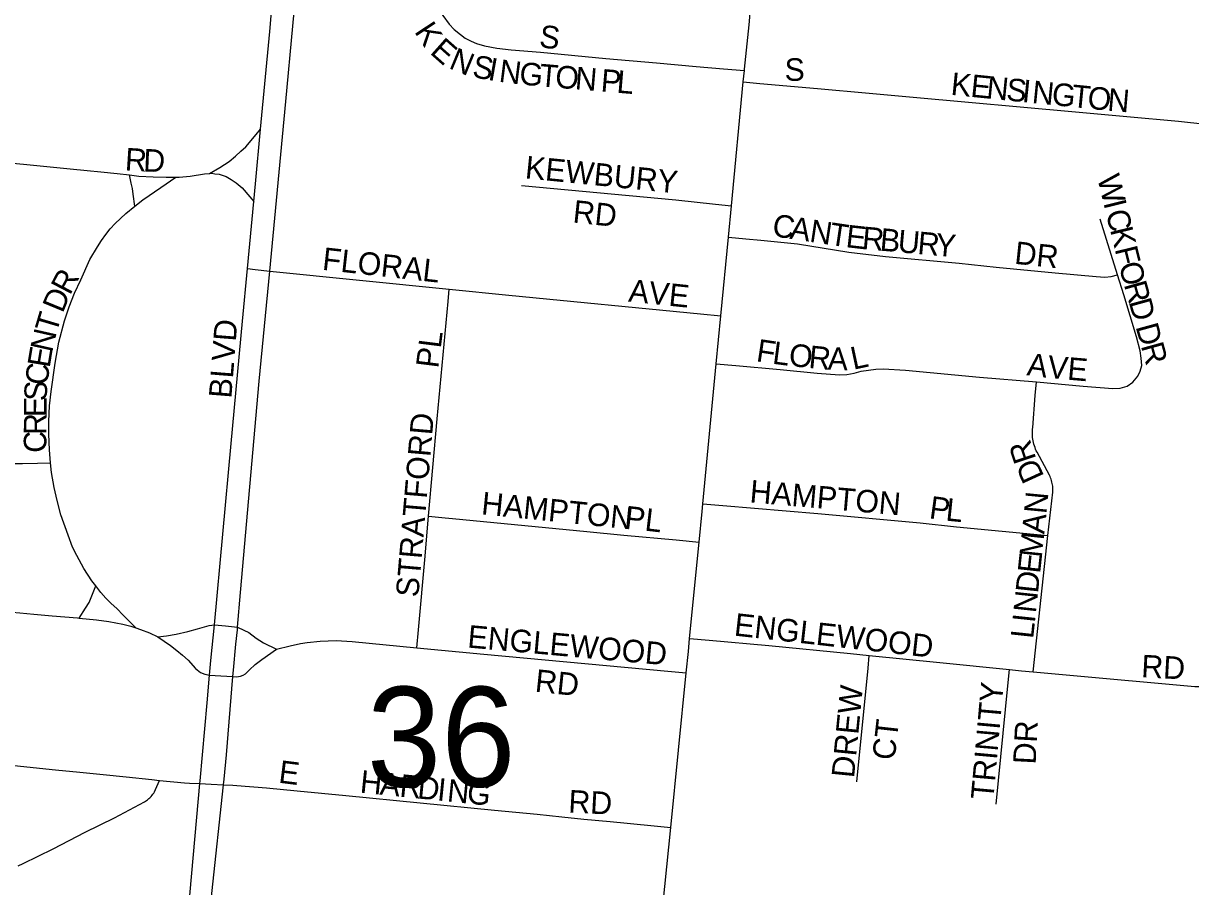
# Model space of a CAD drawing. Extents: x 1410790 to 1770854, y 566777 to 831614.
# Drawn here: x 1601254 to 1603836, y 711039 to 712950 of the extents above; entities that cross this region are included whole.
import ezdxf

# ---------------------------------------------------------------- set-up
doc = ezdxf.new("R2010")
doc.units = 0
for name, color, linetype in [('GM_X_City_Street', 7, 'Continuous'), ('GM_X_City_Street_Text', 7, 'Continuous'), ('GM_X_Section_Text', 7, 'Continuous'), ('GM_X_State_Route', 7, 'Continuous')]:
    doc.layers.add(name, color=color, linetype=linetype)

msp = doc.modelspace()

# ---------------------------------------------------------------- linework, layer by layer
at = {"layer": 'GM_X_City_Street'}
for points in [[(1601778.7, 712715.5), (1601799, 712931.8), (1601814.5, 713115.5)], [(1601798.8, 712401.6), (1601834.6, 712776.7), (1601865.2, 713110.9)], [(1602161.3, 712994.4), (1602167.7, 712986.1), (1602195.8, 712948), (1602206.9, 712936.2), (1602220.8, 712924.8), (1602231.5, 712917), (1602244.1, 712910.3), (1602256.2, 712905.4), (1602274.1, 712899.8), (1602300.9, 712894.7), (1602333, 712891.4), (1602398, 712885.7), (1602542.3, 712872.1), (1602654.3, 712862.3), (1602741.8, 712854.6), (1602802.9, 712849.3), (1602848.8, 712845.3)], [(1602846.4, 712820.2), (1602882.9, 712816.9), (1603010.5, 712805.5), (1603125.1, 712795.1), (1603222, 712786.7), (1603581.4, 712753.9), (1603694.9, 712743.5), (1603809, 712733.1), (1603922.9, 712720.7), (1604085.5, 712702.9), (1604376.2, 712670.1), (1604592.9, 712646.1), (1604785, 712626.3), (1605102.2, 712593.1)], [(1601665.7, 712617.6), (1601688.7, 712631), (1601708.8, 712644.3), (1601723, 712655.5), (1601735.2, 712666.9), (1601746, 712676.6), (1601769.1, 712704.1), (1601778.7, 712715.5)], [(1601763.7, 712555.6), (1601767.4, 712594.5), (1601778.7, 712715.5)], [(1601021.6, 712660), (1601080.3, 712654.8), (1601141.7, 712649.3), (1601209.6, 712642.7), (1601291.2, 712634.6), (1601357.1, 712628), (1601395.4, 712624.2), (1601425, 712621.2), (1601461.5, 712617.6), (1601488.4, 712614.3)], [(1601500.6, 712545.3), (1601497.1, 712572), (1601495.4, 712584.5), (1601492.7, 712595.9), (1601488.4, 712614.3)], [(1601488.4, 712614.3), (1601509.1, 712611.8), (1601541.4, 712610.1), (1601569.6, 712609), (1601591.5, 712609)], [(1601500.6, 712545.3), (1601518, 712559.2), (1601558, 712586.3), (1601591.5, 712609)], [(1601591.5, 712609), (1601598.5, 712609), (1601622.6, 712611.3), (1601654.8, 712617), (1601665.7, 712617.6)], [(1601665.7, 712617.6), (1601671, 712617.9), (1601677.8, 712617), (1601687, 712615.8), (1601702.4, 712610.5), (1601713.7, 712604.1), (1601724.5, 712596.7), (1601737.7, 712585.9), (1601754.9, 712565.8), (1601763.7, 712555.6)], [(1602355.5, 712591), (1602697, 712558.8), (1602785.1, 712549.3), (1602820.2, 712545.5)], [(1601314.3, 711977.2), (1601311.4, 712005.5), (1601310.6, 712040.2), (1601310.6, 712068.2), (1601312.1, 712102.9), (1601315.1, 712134.6), (1601324.2, 712197.3), (1601332.3, 712244), (1601345, 712291.4), (1601355.1, 712322.4), (1601367.1, 712352.8), (1601380.9, 712382.4), (1601401.2, 712426.8), (1601418, 712455.1), (1601426.6, 712468.9), (1601436, 712482.1), (1601446.2, 712494.8), (1601457.1, 712506.8), (1601480.4, 712529.1), (1601500.6, 712545.3)], [(1601749.6, 712407), (1601763.7, 712555.6)], [(1603674.2, 712392.8), (1603635.6, 712516.6)], [(1602813.5, 712476.2), (1602852.3, 712473), (1602885, 712470.2), (1602966.4, 712461.4), (1603079.7, 712443.4), (1603161.1, 712433.9), (1603324.1, 712418.7), (1603405.6, 712410.3), (1603536.1, 712397.8), (1603626.6, 712389.6), (1603645.9, 712388.1), (1603659.7, 712389.1), (1603674.2, 712392.8)], [(1601676.8, 711618.6), (1601713.3, 712019.6), (1601738.3, 712290.8), (1601749.6, 712407)], [(1601727.4, 711613.1), (1601734.4, 711689.8), (1601775.6, 712157.6), (1601798.8, 712401.6)], [(1601749.6, 712407), (1601766.7, 712405.2), (1601798.8, 712401.6)], [(1601798.8, 712401.6), (1602196.1, 712361.2)], [(1603718.7, 712168.9), (1603724.3, 712180), (1603727.9, 712192.5), (1603726.7, 712208.6), (1603724.1, 712224.6), (1603716.4, 712256), (1603687.8, 712349.1), (1603674.2, 712392.8)], [(1602150, 711859.1), (1602169.3, 712074.1), (1602193.6, 712334.3), (1602196.1, 712361.2)], [(1602196.1, 712361.2), (1602327.7, 712348.2), (1602751.7, 712306.6), (1602796.9, 712302.2)], [(1602786.7, 712196.2), (1602829.6, 712192.4), (1602927.9, 712183.9), (1603009.9, 712175.6), (1603059, 712172), (1603075.4, 712172.3), (1603091.4, 712175.3), (1603107.3, 712179.8), (1603139.6, 712184.5), (1603155.9, 712185.2), (1603205.1, 712182.4), (1603368.9, 712166.9), (1603494.7, 712156)], [(1603520.3, 711816.3), (1603531, 711912.2), (1603531.2, 711915.4), (1603531.2, 711918.6), (1603531.1, 711921.9), (1603530.8, 711925.1), (1603530.4, 711928.3), (1603529.8, 711931.5), (1603529.1, 711934.6), (1603528.2, 711937.7), (1603527.2, 711940.7), (1603526.1, 711943.8), (1603524.8, 711946.7), (1603523.3, 711949.6), (1603496.1, 712000.4), (1603494.4, 712003.8), (1603492.9, 712007.3), (1603491.6, 712010.8), (1603490.4, 712014.4), (1603489.3, 712018.1), (1603488.3, 712021.7), (1603487.5, 712025.4), (1603486.9, 712029.2), (1603486.4, 712032.9), (1603486.1, 712036.7), (1603485.9, 712040.5), (1603485.8, 712044.3), (1603485.9, 712048.1), (1603486.2, 712051.9), (1603486.6, 712055.6), (1603492.2, 712126), (1603494.7, 712156)], [(1603494.7, 712156), (1603598.3, 712147), (1603663.7, 712141.6), (1603679.9, 712142.2), (1603695.6, 712146.6), (1603707.7, 712155.7), (1603718.7, 712168.9)], [(1600937, 712026.2), (1600949.2, 712020.4), (1600965.1, 712012.4), (1600983.5, 712005.2), (1601002.6, 712000.4), (1601025.8, 711996.4), (1601052.9, 711993.3), (1601107.2, 711986.9), (1601156.7, 711982.1), (1601190.2, 711978.9), (1601230.9, 711975.7), (1601251.7, 711975.7), (1601285.2, 711976.5), (1601314.3, 711977.2)], [(1601414.1, 711704.5), (1601405.5, 711715.8), (1601387.7, 711743.3), (1601372.2, 711772.1), (1601362.7, 711790.3), (1601352.8, 711817), (1601336.8, 711861.9), (1601328.7, 711893.8), (1601321.9, 711922.5), (1601316.4, 711956), (1601314.3, 711977.2)], [(1602757.1, 711886.6), (1602801.3, 711882.9), (1603011.3, 711865), (1603237.4, 711844.4), (1603318, 711835.7), (1603520.3, 711816.3)], [(1602124.6, 711567.6), (1602128.2, 711607.4), (1602142.8, 711770.1), (1602149.3, 711850.9), (1602150, 711859.1)], [(1602150, 711859.1), (1602186.9, 711855.2), (1602203.3, 711853.5), (1602500.1, 711824.9), (1602582.4, 711817.2), (1602697.8, 711806.4), (1602748.8, 711801.5)], [(1603487.6, 711514.7), (1603520.3, 711816.3)], [(1601377.6, 711633.6), (1601391.3, 711655.4), (1601399.2, 711668.1), (1601405.7, 711682.7), (1601414.1, 711704.5)], [(1601502.5, 711612.1), (1601474.3, 711640.8), (1601461.1, 711653.7), (1601447.7, 711666.1), (1601436.1, 711677.6), (1601425.3, 711689.8), (1601414.1, 711704.5)], [(1600886.5, 711677.2), (1600904.3, 711675.5), (1600923.1, 711674), (1600967.5, 711669.5), (1601027.4, 711663.5), (1601076.8, 711659.5), (1601123.7, 711655.7), (1601166.2, 711652.5), (1601212.3, 711647.9), (1601246, 711644.7), (1601277.4, 711641.8), (1601317.3, 711638.3), (1601373.7, 711633.9), (1601377.6, 711633.6)], [(1601377.6, 711633.6), (1601415.4, 711629.6), (1601442.8, 711625.9), (1601473.8, 711619.7), (1601491.9, 711615.3), (1601502.5, 711612.1)], [(1601502.5, 711612.1), (1601512.9, 711608.4), (1601532.9, 711600.6), (1601551.4, 711592.1)], [(1601551.4, 711592.1), (1601570.8, 711594.5), (1601591.6, 711597.7), (1601617.6, 711603.6), (1601638.9, 711609.3), (1601654.4, 711613.9), (1601665.2, 711617.1), (1601676.8, 711618.6)], [(1601665.6, 711507.1), (1601668.8, 711539.4), (1601676.8, 711618.6)], [(1601676.8, 711618.6), (1601701.4, 711616.4)], [(1601701.4, 711616.4), (1601727.4, 711613.1)], [(1601717.4, 711504), (1601718.7, 711518.1), (1601724.1, 711575.4), (1601727.4, 711607.7), (1601727.4, 711613.1)], [(1601727.4, 711613.1), (1601741.5, 711607), (1601752.5, 711601.2), (1601768.7, 711589.3), (1601785.4, 711578.4), (1601813.7, 711564.4)], [(1601551.4, 711592.1), (1601579.7, 711573), (1601593.5, 711561.6), (1601606.3, 711551.4), (1601618.4, 711540.3), (1601635, 711522), (1601645.4, 711513.3), (1601655.1, 711509), (1601665.6, 711507.1)], [(1602727.7, 711588), (1602770.9, 711584.2), (1602902.6, 711572.4), (1603083.6, 711554.7), (1603124.9, 711550.6)], [(1601717.4, 711504), (1601725.2, 711503.6), (1601734.3, 711505), (1601740.1, 711507.2), (1601745.1, 711510.1), (1601754.1, 711518.8), (1601766.8, 711530.6), (1601781.5, 711541.9), (1601813.7, 711564.4)], [(1601813.7, 711564.4), (1601844.4, 711572.2), (1601867, 711577.4), (1601881.7, 711579.6), (1601910.7, 711582.2), (1601945.9, 711583.5), (1601980.9, 711581.6), (1602124.6, 711567.6)], [(1602124.6, 711567.6), (1602272.2, 711553.2), (1602679.6, 711515.6), (1602720.1, 711511.9)], [(1603097.8, 711271.1), (1603122.2, 711522.4), (1603124.9, 711550.6)], [(1603124.9, 711550.6), (1603281, 711534.9), (1603434.8, 711519.7)], [(1603405.8, 711221.9), (1603431.3, 711483.8), (1603434.8, 711519.7)], [(1603434.8, 711519.7), (1603462, 711517), (1603487.6, 711514.7)], [(1603487.6, 711514.7), (1603560.7, 711508), (1603845.3, 711482.3), (1603860.8, 711482), (1603879.8, 711484), (1603894.2, 711487.3), (1603935.8, 711506.2), (1603972.6, 711522.6)], [(1601644.4, 711267), (1601645, 711272.9), (1601660.5, 711445.6), (1601665.6, 711507.1)], [(1601665.6, 711507.1), (1601690.5, 711505.4)], [(1601690.5, 711505.4), (1601717.4, 711504)], [(1601696.6, 711264.7), (1601697.9, 711277.1), (1601703.6, 711330.4), (1601717.4, 711504)], [(1600541.3, 711374.7), (1600592, 711369.6), (1600706.1, 711358.9), (1600742.6, 711355.5), (1600784.5, 711351.5), (1600867.4, 711343.8), (1600980.4, 711331.6), (1601045.5, 711325.2), (1601191.2, 711311.7), (1601325.1, 711297.9), (1601378.9, 711292.3), (1601430.3, 711287), (1601481.6, 711281.7), (1601537.8, 711276), (1601555.1, 711274.2)], [(1601242.8, 711084.8), (1601253.8, 711089.9), (1601319.8, 711122.6), (1601390.6, 711159.5), (1601455.2, 711191.3), (1601521.6, 711226.8), (1601526, 711229.6), (1601528.3, 711231.3), (1601529.9, 711232.6), (1601531.6, 711233.9), (1601533.5, 711235.6), (1601536.4, 711238.5), (1601539, 711241.5), (1601540.5, 711243.4), (1601541.5, 711244.9), (1601542.2, 711245.9), (1601543, 711247.1), (1601543.9, 711248.8), (1601546.3, 711254.3), (1601555.1, 711274.2)], [(1601555.1, 711274.2), (1601610.4, 711268.5), (1601621.6, 711267.7), (1601644.4, 711267)], [(1601615.4, 710945), (1601644.4, 711267)], [(1601644.4, 711267), (1601669.6, 711266.1), (1601696.6, 711264.7)], [(1601663.7, 710940.6), (1601671, 711023.6), (1601696.6, 711264.7)], [(1601696.6, 711264.7), (1601717.4, 711263.6), (1601725.9, 711263.2), (1601791.4, 711257.4), (1601859.9, 711250.9), (1601967.3, 711240.8), (1602295.8, 711208.4), (1602390.4, 711199.1), (1602445, 711193.7), (1602494, 711188.7), (1602551.8, 711183), (1602589.2, 711179.4), (1602656.8, 711172.7), (1602685.8, 711169.8)]]:
    msp.add_lwpolyline(points, dxfattribs=at)
at = {"layer": 'GM_X_State_Route'}
msp.add_lwpolyline([(1602654.5, 710858.1), (1602685.8, 711169.8), (1602720.1, 711511.9), (1602724.8, 711559.6), (1602727.7, 711588), (1602748.8, 711801.5), (1602755.5, 711869.5), (1602757.1, 711886.6), (1602786.7, 712196.2), (1602796.9, 712302.2), (1602813.5, 712476.2), (1602820.2, 712545.5), (1602846.4, 712820.2), (1602848.8, 712845.3), (1602849.2, 712848.7), (1602859.4, 712946.5), (1602868.8, 713060.8)], dxfattribs=at)

# ---------------------------------------------------------------- texts
at = {"layer": 'GM_X_City_Street_Text'}
for s, rotation, p in [('K', 303.5627, (1602117.6, 712931.5)), ('S', 352.8783, (1602393.3, 712897.3)), ('E', 318.4859, (1602151.3, 712884.1)), ('N', 337.4623, (1602192.9, 712851.2)), ('S', 350.1365, (1602245.1, 712831)), ('I', 349.8046, (1602279.7, 712825)), ('N', 352.8025, (1602304.2, 712820.6)), ('G', 354.4515, (1602349.4, 712814.9)), ('T', 355.1258, (1602393.8, 712810.6)), ('O', 355.2289, (1602429, 712807.6)), ('N', 355.2407, (1602472.8, 712804)), ('S', 0, (1602937.7, 712822.5)), ('P', 355.2137, (1602529.9, 712799.2)), ('L', 355.2533, (1602565, 712796.3)), ('K', 354.2416, (1603303.9, 712791.7)), ('E', 354.2615, (1603347.6, 712787.3)), ('N', 354.2416, (1603382.7, 712783.7)), ('S', 354.2615, (1603426.5, 712779.3)), ('I', 354.2198, (1603461.5, 712775.8)), ('N', 354.2598, (1603483.4, 712773.6)), ('G', 354.2416, (1603527.2, 712769.2)), ('T', 354.2615, (1603571, 712764.8)), ('O', 354.2416, (1603606, 712761.2)), ('N', 355.0372, (1603650.5, 712756.7)), ('R', 356.4524, (1601477.6, 712624.5)), ('D', 357.7383, (1601518.4, 712622)), ('KEWBURY', 354.2894, (1602362.3, 712606.9)), ('W', 283.7671, (1603628.9, 712608.6)), ('RD', 353.9946, (1602467.8, 712509.1)), ('I', 283.7987, (1603642.5, 712553)), ('C', 351.2963, (1602908.4, 712479.2)), ('A', 351.2957, (1602947.5, 712473.3)), ('N', 351.2957, (1602991, 712466.6)), ('C', 283.7829, (1603647.7, 712531.6)), ('T', 351.5662, (1603034.7, 712459.9)), ('E', 353.6134, (1603071.5, 712454.5)), ('R', 354.864, (1603107.7, 712450.4)), ('B', 354.9007, (1603147.1, 712446.9)), ('U', 354.9023, (1603186.6, 712443.3)), ('K', 283.7712, (1603657.2, 712493.2)), ('R', 354.9007, (1603230.4, 712439.4)), ('Y', 354.9023, (1603269.8, 712435.9)), ('DR', 353.9946, (1603444.7, 712417.7)), ('FLORAL', 353.6594, (1601913.6, 712404.5)), ('F', 283.7686, (1603667.6, 712450.4)), ('O', 284.8811, (1603676.3, 712415.2)), ('R', 62.4575, (1601357, 712346.4)), ('D', 67.6222, (1601340.8, 712306.8)), ('AVE', 354.0969, (1602591.1, 712334.1)), ('R', 285.7844, (1603687.8, 712371.9)), ('D', 285.42, (1603698.5, 712333.8)), ('T', 73.4918, (1601327, 712261.8)), ('BLVD', 85.4883, (1601713.9, 712118.7)), ('D', 285.3989, (1603713.7, 712278.7)), ('N', 77.1938, (1601317.5, 712219.8)), ('PL', 82.8783, (1602171.6, 712185.1)), ('E', 80.614, (1601311.9, 712185.8)), ('F', 351.3328, (1602873.2, 712202)), ('L', 352.553, (1602909.1, 712196.6)), ('O', 354.158, (1602945.6, 712191.8)), ('R', 354.35, (1602989.5, 712187.3)), ('A', 358.1238, (1603032.5, 712183.2)), ('L', 12.0374, (1603089.7, 712182.9)), ('R', 285.4159, (1603725.4, 712236.3)), ('A', 352.6798, (1603472.1, 712171.1)), ('V', 354.778, (1603517.8, 712165.3)), ('E', 355.0229, (1603561.8, 712161.3)), ('C', 82.6461, (1601306.9, 712147)), ('S', 87.2945, (1601305.3, 712112.9)), ('E', 89.6721, (1601305.1, 712078.2)), ('R', 89.6843, (1601304.9, 712038.7)), ('STRATFORD', 85.1229, (1602127.5, 711678.4)), ('C', 89.6843, (1601304.7, 711999.1)), ('R', 108.458, (1603494.8, 711985.9)), ('D', 114.5962, (1603512.6, 711947.2)), ('HAMPTON', 355.0307, (1602859.3, 711889.7)), ('HAMPTON', 354.2073, (1602265.5, 711863.3)), ('P', 352.1598, (1603255.9, 711854.4)), ('L', 354.1161, (1603292.6, 711849.4)), ('N', 84.4964, (1603516.8, 711862.7)), ('PL', 353.2931, (1602582.4, 711832.5)), ('A', 83.9093, (1603512.1, 711818.4)), ('M', 83.9052, (1603506.5, 711765.9)), ('E', 83.9178, (1603502.8, 711730.9)), ('D', 83.9132, (1603498.1, 711687.2)), ('N', 83.9093, (1603493.4, 711643.4)), ('ENGLEWOOD', 353.5883, (1602824.5, 711594.9)), ('I', 83.9109, (1603491.1, 711621.5)), ('ENGLEWOOD', 354.8646, (1602235, 711568.4)), ('L', 83.9223, (1603487.4, 711586.5)), ('RD', 356.989, (1603725.8, 711502.5)), ('RD', 353.9934, (1602384.2, 711470.7)), ('DREW', 84.4309, (1603091.2, 711278.4)), ('TRINITY', 84.8967, (1603399.3, 711230)), ('CT', 83.6625, (1603181.1, 711317.5)), ('DR', 86.989, (1603492.9, 711308.8)), ('E', 352.8514, (1601816.9, 711269.3)), ('H', 354.1981, (1601997.1, 711247.3)), ('A', 354.2253, (1602040.9, 711242.8)), ('R', 354.1855, (1602084.7, 711238.4)), ('D', 354.2253, (1602124.1, 711234.4)), ('I', 354.1763, (1602167.9, 711230)), ('N', 354.2029, (1602189.8, 711227.7)), ('G', 354.2253, (1602233.6, 711223.3)), ('RD', 356.989, (1602458.6, 711203.3))]:
    msp.add_text(s, height=50, rotation=rotation, dxfattribs=at).set_placement(p)
at = {"layer": 'GM_X_Section_Text'}
msp.add_text('36', height=221, rotation=0, dxfattribs=at).set_placement((1602013.7, 711260.3))

doc.saveas('drawing.dxf')
